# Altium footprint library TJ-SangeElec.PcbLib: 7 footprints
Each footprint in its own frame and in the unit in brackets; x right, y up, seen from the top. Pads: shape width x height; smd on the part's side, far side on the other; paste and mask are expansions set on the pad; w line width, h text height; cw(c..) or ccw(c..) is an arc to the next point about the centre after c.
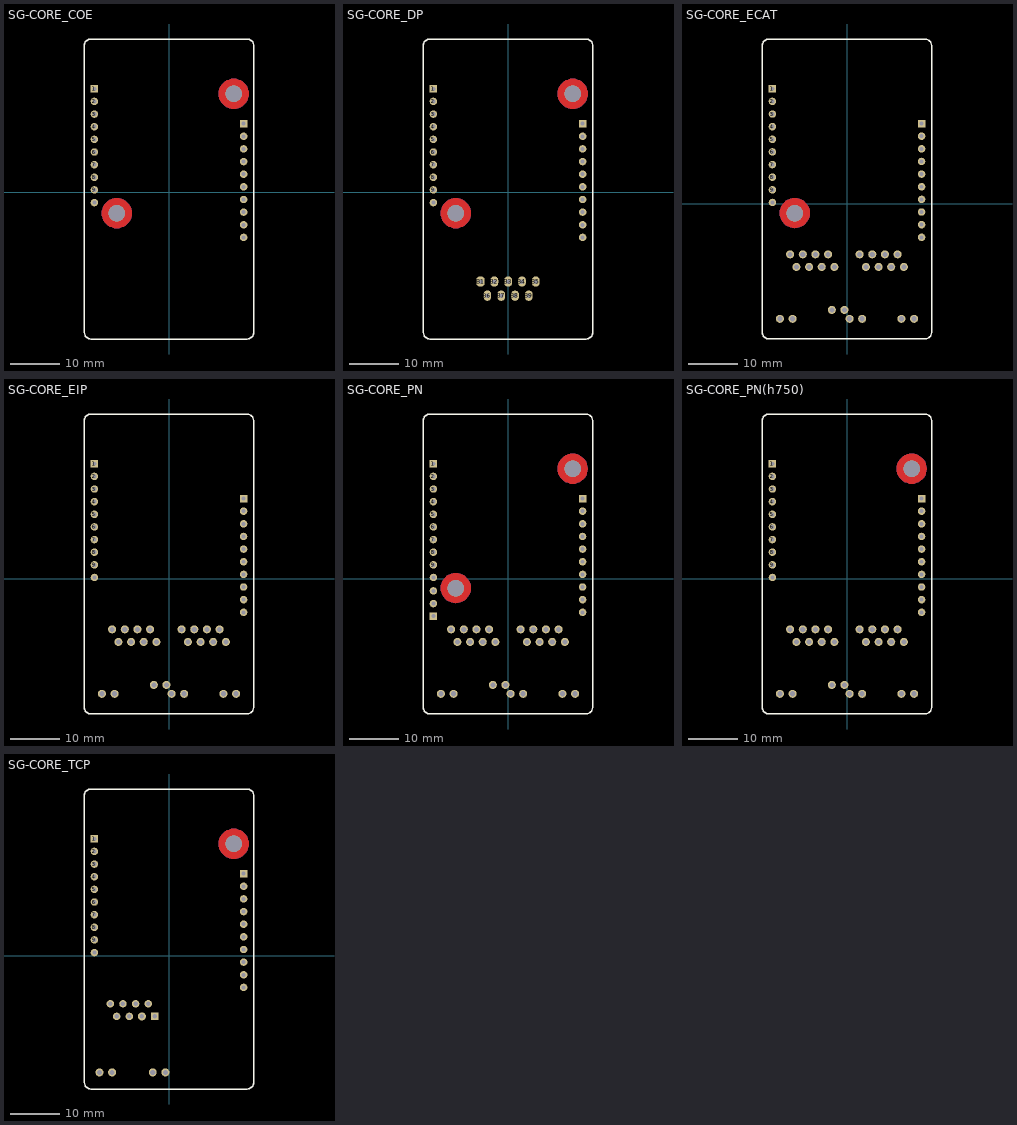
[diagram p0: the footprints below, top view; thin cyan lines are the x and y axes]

## SG-CORE_COE [mm] "CANOPEN核心板"
pads (20):
  rect 1.5x1.5 hole 0.8: 1(-15,20.783) 11(15,13.783)
  round 1.5 hole 0.8: 2(-15,18.243) 3(-15,15.703) 4(-15,13.163) 5(-15,10.623) 6(-15,8.083) 7(-15,5.543) 8(-15,3.003) 9(-15,0.463) 10(-15,-2.077) 12(15,11.243) 13(15,8.703) 14(15,6.163) 15(15,3.623) 16(15,1.083) 17(15,-1.457) 18(15,-3.997) 19(15,-6.537) 20(15,-9.077)
via -10.5,-4.217 diameter 3.3 hole 3.3
via 13,19.783 diameter 3.3 hole 3.3
Top Layer:
  pour cut-out: -13.509,-4.217 -13.472,-4.688 -13.362,-5.147 -13.181,-5.584 -12.935,-5.986 -12.628,-6.345 -12.269,-6.652 -11.866,-6.899 -11.43,-7.079 -10.971,-7.19 -10.5,-7.227 -10.029,-7.19 -9.57,-7.079 -9.134,-6.899 -8.731,-6.652 -8.372,-6.345 -8.065,-5.986 -7.819,-5.584 -7.638,-5.147 -7.528,-4.688 -7.491,-4.217 -7.528,-3.747 -7.638,-3.287 -7.819,-2.851 -8.065,-2.449 -8.372,-2.09 -8.731,-1.783 -9.134,-1.536 -9.57,-1.355 -10.029,-1.245 -10.5,-1.208 -10.971,-1.245 -11.43,-1.355 -11.866,-1.536 -12.269,-1.783 -12.628,-2.09 -12.935,-2.449 -13.181,-2.851 -13.362,-3.287 -13.472,-3.747
  pour cut-out: 9.991,19.783 10.028,19.312 10.138,18.853 10.319,18.416 10.565,18.014 10.872,17.655 11.231,17.348 11.634,17.101 12.07,16.921 12.529,16.81 13,16.773 13.471,16.81 13.93,16.921 14.366,17.101 14.769,17.348 15.128,17.655 15.435,18.014 15.681,18.416 15.862,18.853 15.972,19.312 16.009,19.783 15.972,20.253 15.862,20.713 15.681,21.149 15.435,21.551 15.128,21.91 14.769,22.217 14.366,22.464 13.93,22.645 13.471,22.755 13,22.792 12.529,22.755 12.07,22.645 11.634,22.464 11.231,22.217 10.872,21.91 10.565,21.551 10.319,21.149 10.138,20.713 10.028,20.253
Bottom Layer:
  pour cut-out: -13.509,-4.217 -13.472,-4.688 -13.362,-5.147 -13.181,-5.584 -12.935,-5.986 -12.628,-6.345 -12.269,-6.652 -11.866,-6.899 -11.43,-7.079 -10.971,-7.19 -10.5,-7.227 -10.029,-7.19 -9.57,-7.079 -9.134,-6.899 -8.731,-6.652 -8.372,-6.345 -8.065,-5.986 -7.819,-5.584 -7.638,-5.147 -7.528,-4.688 -7.491,-4.217 -7.528,-3.747 -7.638,-3.287 -7.819,-2.851 -8.065,-2.449 -8.372,-2.09 -8.731,-1.783 -9.134,-1.536 -9.57,-1.355 -10.029,-1.245 -10.5,-1.208 -10.971,-1.245 -11.43,-1.355 -11.866,-1.536 -12.269,-1.783 -12.628,-2.09 -12.935,-2.449 -13.181,-2.851 -13.362,-3.287 -13.472,-3.747
  pour cut-out: 9.991,19.783 10.028,19.312 10.138,18.853 10.319,18.416 10.565,18.014 10.872,17.655 11.231,17.348 11.634,17.101 12.07,16.921 12.529,16.81 13,16.773 13.471,16.81 13.93,16.921 14.366,17.101 14.769,17.348 15.128,17.655 15.435,18.014 15.681,18.416 15.862,18.853 15.972,19.312 16.009,19.783 15.972,20.253 15.862,20.713 15.681,21.149 15.435,21.551 15.128,21.91 14.769,22.217 14.366,22.464 13.93,22.645 13.471,22.755 13,22.792 12.529,22.755 12.07,22.645 11.634,22.464 11.231,22.217 10.872,21.91 10.565,21.551 10.319,21.149 10.138,20.713 10.028,20.253
Top Overlay:
  lines w0.254: -17.007,29.505 cw(c-15.737,29.505) -15.737,30.775 ; -17,-28.222 -17,29.512 ; -16.993,-28.222 ccw(c-15.723,-28.222) -15.723,-29.492 ; -15.73,30.79 15.723,30.79 ; -15.697,-29.492 0.025,-29.492 ; -0.152,-29.492 15.621,-29.492 ; 15.723,-29.492 ccw(c15.723,-28.222) 16.993,-28.222 ; 15.723,30.772 cw(c15.723,29.502) 16.993,29.502 ; 17,-28.222 17,29.509

## SG-CORE_DP [mm] "Profibus DP核心板"
pads (29):
  rect 1.5x1.5 hole 0.8: 1(-15,20.783) 11(15,13.783)
  round 1.5 hole 0.8: 2(-15,18.243) 3(-15,15.703) 4(-15,13.163) 5(-15,10.623) 6(-15,8.083) 7(-15,5.543) 8(-15,3.003) 9(-15,0.463) 10(-15,-2.077) 12(15,11.243) 13(15,8.703) 14(15,6.163) 15(15,3.623) 16(15,1.083) 17(15,-1.457) 18(15,-3.997) 19(15,-6.537) 20(15,-9.077)
  oct 1.575x2.083 hole 0.889: B1(-5.521,-17.946)
  oval 1.575x2.083 hole 0.889: B2(-2.748,-17.946) B3(0.025,-17.946) B4(2.797,-17.946) B5(5.57,-17.946) B7(-1.372,-20.783) B8(1.4,-20.783) B9(4.173,-20.783)
  oval 1.524x2.083 hole 0.889: B6(-4.145,-20.783)
via 13,19.783 diameter 3.3 hole 3.3
via -10.5,-4.217 diameter 3.3 hole 3.3
Top Layer:
  pour cut-out: 9.991,19.783 10.028,19.312 10.138,18.853 10.319,18.416 10.565,18.014 10.872,17.655 11.231,17.348 11.634,17.101 12.07,16.921 12.529,16.81 13,16.773 13.471,16.81 13.93,16.921 14.366,17.101 14.769,17.348 15.128,17.655 15.435,18.014 15.681,18.416 15.862,18.853 15.972,19.312 16.009,19.783 15.972,20.253 15.862,20.713 15.681,21.149 15.435,21.551 15.128,21.91 14.769,22.217 14.366,22.464 13.93,22.645 13.471,22.755 13,22.792 12.529,22.755 12.07,22.645 11.634,22.464 11.231,22.217 10.872,21.91 10.565,21.551 10.319,21.149 10.138,20.713 10.028,20.253
  pour cut-out: -13.509,-4.217 -13.472,-4.688 -13.362,-5.147 -13.181,-5.584 -12.935,-5.986 -12.628,-6.345 -12.269,-6.652 -11.866,-6.899 -11.43,-7.079 -10.971,-7.19 -10.5,-7.227 -10.029,-7.19 -9.57,-7.079 -9.134,-6.899 -8.731,-6.652 -8.372,-6.345 -8.065,-5.986 -7.819,-5.584 -7.638,-5.147 -7.528,-4.688 -7.491,-4.217 -7.528,-3.747 -7.638,-3.287 -7.819,-2.851 -8.065,-2.449 -8.372,-2.09 -8.731,-1.783 -9.134,-1.536 -9.57,-1.355 -10.029,-1.245 -10.5,-1.208 -10.971,-1.245 -11.43,-1.355 -11.866,-1.536 -12.269,-1.783 -12.628,-2.09 -12.935,-2.449 -13.181,-2.851 -13.362,-3.287 -13.472,-3.747
Bottom Layer:
  pour cut-out: 9.991,19.783 10.028,19.312 10.138,18.853 10.319,18.416 10.565,18.014 10.872,17.655 11.231,17.348 11.634,17.101 12.07,16.921 12.529,16.81 13,16.773 13.471,16.81 13.93,16.921 14.366,17.101 14.769,17.348 15.128,17.655 15.435,18.014 15.681,18.416 15.862,18.853 15.972,19.312 16.009,19.783 15.972,20.253 15.862,20.713 15.681,21.149 15.435,21.551 15.128,21.91 14.769,22.217 14.366,22.464 13.93,22.645 13.471,22.755 13,22.792 12.529,22.755 12.07,22.645 11.634,22.464 11.231,22.217 10.872,21.91 10.565,21.551 10.319,21.149 10.138,20.713 10.028,20.253
  pour cut-out: -13.509,-4.217 -13.472,-4.688 -13.362,-5.147 -13.181,-5.584 -12.935,-5.986 -12.628,-6.345 -12.269,-6.652 -11.866,-6.899 -11.43,-7.079 -10.971,-7.19 -10.5,-7.227 -10.029,-7.19 -9.57,-7.079 -9.134,-6.899 -8.731,-6.652 -8.372,-6.345 -8.065,-5.986 -7.819,-5.584 -7.638,-5.147 -7.528,-4.688 -7.491,-4.217 -7.528,-3.747 -7.638,-3.287 -7.819,-2.851 -8.065,-2.449 -8.372,-2.09 -8.731,-1.783 -9.134,-1.536 -9.57,-1.355 -10.029,-1.245 -10.5,-1.208 -10.971,-1.245 -11.43,-1.355 -11.866,-1.536 -12.269,-1.783 -12.628,-2.09 -12.935,-2.449 -13.181,-2.851 -13.362,-3.287 -13.472,-3.747
Top Overlay:
  lines w0.254: -17.007,29.505 cw(c-15.737,29.505) -15.737,30.775 ; -17,-28.222 -17,29.512 ; -16.993,-28.222 ccw(c-15.723,-28.222) -15.723,-29.492 ; -15.73,30.79 15.723,30.79 ; -15.697,-29.492 0.025,-29.492 ; -0.152,-29.492 15.621,-29.492 ; 15.723,-29.492 ccw(c15.723,-28.222) 16.993,-28.222 ; 15.723,30.772 cw(c15.723,29.502) 16.993,29.502 ; 17,-28.222 17,29.509

## SG-CORE_ECAT [mm] "EtherCAT核心板"
pads (44):
  rect 1.5x1.5 hole 0.8: 1(-15,23.122) 11(15,16.122)
  round 1.5 hole 0.8: 2(-15,20.582) 3(-15,18.042) 4(-15,15.502) 5(-15,12.962) 6(-15,10.422) 7(-15,7.882) 8(-15,5.342) 9(-15,2.802) 10(-15,0.262) 12(15,13.582) 13(15,11.042) 14(15,8.502) 15(15,5.962) 16(15,3.422) 17(15,0.882) 18(15,-1.658) 19(15,-4.198) 20(15,-6.738)
  round 1.62 hole 1.02: A1(11.43,-12.708) A2(10.16,-10.168) A3(8.89,-12.708) A4(7.62,-10.168) A5(6.35,-12.708) A6(5.08,-10.168) A7(3.81,-12.708) A8(2.54,-10.168) A9(13.487,-23.122) A10(10.947,-23.122) A11(3.048,-23.122) A12(0.508,-23.122) B1(-2.54,-12.708) B2(-3.81,-10.168) B3(-5.08,-12.708) B4(-6.35,-10.168) B5(-7.62,-12.708) B6(-8.89,-10.168) B7(-10.16,-12.708) B8(-11.43,-10.168) B9(-0.508,-21.344) B10(-3.048,-21.344) B11(-10.947,-23.122) B12(-13.487,-23.122)
via -10.5,-1.878 diameter 3.3 hole 3.3
Top Layer:
  pour cut-out: -13.509,-1.878 -13.472,-2.349 -13.362,-2.808 -13.181,-3.244 -12.935,-3.647 -12.628,-4.006 -12.269,-4.313 -11.866,-4.559 -11.43,-4.74 -10.971,-4.85 -10.5,-4.887 -10.029,-4.85 -9.57,-4.74 -9.134,-4.559 -8.731,-4.313 -8.372,-4.006 -8.065,-3.647 -7.819,-3.244 -7.638,-2.808 -7.528,-2.349 -7.491,-1.878 -7.528,-1.407 -7.638,-0.948 -7.819,-0.512 -8.065,-0.109 -8.372,0.25 -8.731,0.556 -9.134,0.803 -9.57,0.984 -10.029,1.094 -10.5,1.131 -10.971,1.094 -11.43,0.984 -11.866,0.803 -12.269,0.556 -12.628,0.25 -12.935,-0.109 -13.181,-0.512 -13.362,-0.948 -13.472,-1.407
Bottom Layer:
  pour cut-out: -13.509,-1.878 -13.472,-2.349 -13.362,-2.808 -13.181,-3.244 -12.935,-3.647 -12.628,-4.006 -12.269,-4.313 -11.866,-4.559 -11.43,-4.74 -10.971,-4.85 -10.5,-4.887 -10.029,-4.85 -9.57,-4.74 -9.134,-4.559 -8.731,-4.313 -8.372,-4.006 -8.065,-3.647 -7.819,-3.244 -7.638,-2.808 -7.528,-2.349 -7.491,-1.878 -7.528,-1.407 -7.638,-0.948 -7.819,-0.512 -8.065,-0.109 -8.372,0.25 -8.731,0.556 -9.134,0.803 -9.57,0.984 -10.029,1.094 -10.5,1.131 -10.971,1.094 -11.43,0.984 -11.866,0.803 -12.269,0.556 -12.628,0.25 -12.935,-0.109 -13.181,-0.512 -13.362,-0.948 -13.472,-1.407
Top Overlay:
  lines w0.254: -17,-25.908 ccw(c-15.73,-25.908) -15.73,-27.178 ; -17,-25.883 -17,31.844 ; -17,31.852 cw(c-15.73,31.852) -15.73,33.122 15.723,33.122 cw(c15.723,31.852) 16.993,31.852 ; -15.672,-27.186 15.781,-27.186 ; 15.723,-27.178 ccw(c15.723,-25.908) 16.993,-25.908 ; 17,-25.908 17,31.841

## SG-CORE_EIP [mm] "EtherNet核心板"
pads (44):
  rect 1.5x1.5 hole 0.8: 1(-15,23.122) 11(15,16.122)
  round 1.5 hole 0.8: 2(-15,20.582) 3(-15,18.042) 4(-15,15.502) 5(-15,12.962) 6(-15,10.422) 7(-15,7.882) 8(-15,5.342) 9(-15,2.802) 10(-15,0.262) 12(15,13.582) 13(15,11.042) 14(15,8.502) 15(15,5.962) 16(15,3.422) 17(15,0.882) 18(15,-1.658) 19(15,-4.198) 20(15,-6.738)
  round 1.62 hole 1.02: A1(11.43,-12.708) A2(10.16,-10.168) A3(8.89,-12.708) A4(7.62,-10.168) A5(6.35,-12.708) A6(5.08,-10.168) A7(3.81,-12.708) A8(2.54,-10.168) A9(13.487,-23.122) A10(10.947,-23.122) A11(3.048,-23.122) A12(0.508,-23.122) B1(-2.54,-12.708) B2(-3.81,-10.168) B3(-5.08,-12.708) B4(-6.35,-10.168) B5(-7.62,-12.708) B6(-8.89,-10.168) B7(-10.16,-12.708) B8(-11.43,-10.168) B9(-0.508,-21.344) B10(-3.048,-21.344) B11(-10.947,-23.122) B12(-13.487,-23.122)
Top Overlay:
  lines w0.254: -17,-25.908 ccw(c-15.73,-25.908) -15.73,-27.178 ; -17,-25.883 -17,31.844 ; -17,31.852 cw(c-15.73,31.852) -15.73,33.122 15.723,33.122 cw(c15.723,31.852) 16.993,31.852 ; -15.672,-27.186 15.781,-27.186 ; 15.723,-27.178 ccw(c15.723,-25.908) 16.993,-25.908 ; 17,-25.908 17,31.841

## SG-CORE_PN [mm] "Profinet核心板"
pads (47):
  rect 1.5x1.5 hole 0.8: 1(-15,23.122) 11(15,16.122) 23(-15,-7.526)
  round 1.5 hole 0.8: 2(-15,20.582) 3(-15,18.042) 4(-15,15.502) 5(-15,12.962) 6(-15,10.422) 7(-15,7.882) 8(-15,5.342) 9(-15,2.802) 10(-15,0.262) 12(15,13.582) 13(15,11.042) 14(15,8.502) 15(15,5.962) 16(15,3.422) 17(15,0.882) 18(15,-1.658) 19(15,-4.198) 20(15,-6.738) 21(-15,-2.446) 22(-15,-4.986)
  round 1.62 hole 1.02: A1(11.43,-12.708) A2(10.16,-10.168) A3(8.89,-12.708) A4(7.62,-10.168) A5(6.35,-12.708) A6(5.08,-10.168) A7(3.81,-12.708) A8(2.54,-10.168) A9(13.487,-23.122) A10(10.947,-23.122) A11(3.048,-23.122) A12(0.508,-23.122) B1(-2.54,-12.708) B2(-3.81,-10.168) B3(-5.08,-12.708) B4(-6.35,-10.168) B5(-7.62,-12.708) B6(-8.89,-10.168) B7(-10.16,-12.708) B8(-11.43,-10.168) B9(-0.508,-21.344) B10(-3.048,-21.344) B11(-10.947,-23.122) B12(-13.487,-23.122)
via 13,22.122 diameter 3.3 hole 3.3
via -10.5,-1.878 diameter 3.3 hole 3.3
Top Layer:
  pour cut-out: 9.991,22.122 10.028,21.651 10.138,21.192 10.319,20.756 10.565,20.353 10.872,19.994 11.231,19.687 11.634,19.441 12.07,19.26 12.529,19.15 13,19.113 13.471,19.15 13.93,19.26 14.366,19.441 14.769,19.687 15.128,19.994 15.435,20.353 15.681,20.756 15.862,21.192 15.972,21.651 16.009,22.122 15.972,22.593 15.862,23.052 15.681,23.488 15.435,23.891 15.128,24.25 14.769,24.556 14.366,24.803 13.93,24.984 13.471,25.094 13,25.131 12.529,25.094 12.07,24.984 11.634,24.803 11.231,24.556 10.872,24.25 10.565,23.891 10.319,23.488 10.138,23.052 10.028,22.593
  pour cut-out: -13.509,-1.878 -13.472,-2.349 -13.362,-2.808 -13.181,-3.244 -12.935,-3.647 -12.628,-4.006 -12.269,-4.313 -11.866,-4.559 -11.43,-4.74 -10.971,-4.85 -10.5,-4.887 -10.029,-4.85 -9.57,-4.74 -9.134,-4.559 -8.731,-4.313 -8.372,-4.006 -8.065,-3.647 -7.819,-3.244 -7.638,-2.808 -7.528,-2.349 -7.491,-1.878 -7.528,-1.407 -7.638,-0.948 -7.819,-0.512 -8.065,-0.109 -8.372,0.25 -8.731,0.556 -9.134,0.803 -9.57,0.984 -10.029,1.094 -10.5,1.131 -10.971,1.094 -11.43,0.984 -11.866,0.803 -12.269,0.556 -12.628,0.25 -12.935,-0.109 -13.181,-0.512 -13.362,-0.948 -13.472,-1.407
Bottom Layer:
  pour cut-out: 9.991,22.122 10.028,21.651 10.138,21.192 10.319,20.756 10.565,20.353 10.872,19.994 11.231,19.687 11.634,19.441 12.07,19.26 12.529,19.15 13,19.113 13.471,19.15 13.93,19.26 14.366,19.441 14.769,19.687 15.128,19.994 15.435,20.353 15.681,20.756 15.862,21.192 15.972,21.651 16.009,22.122 15.972,22.593 15.862,23.052 15.681,23.488 15.435,23.891 15.128,24.25 14.769,24.556 14.366,24.803 13.93,24.984 13.471,25.094 13,25.131 12.529,25.094 12.07,24.984 11.634,24.803 11.231,24.556 10.872,24.25 10.565,23.891 10.319,23.488 10.138,23.052 10.028,22.593
  pour cut-out: -13.509,-1.878 -13.472,-2.349 -13.362,-2.808 -13.181,-3.244 -12.935,-3.647 -12.628,-4.006 -12.269,-4.313 -11.866,-4.559 -11.43,-4.74 -10.971,-4.85 -10.5,-4.887 -10.029,-4.85 -9.57,-4.74 -9.134,-4.559 -8.731,-4.313 -8.372,-4.006 -8.065,-3.647 -7.819,-3.244 -7.638,-2.808 -7.528,-2.349 -7.491,-1.878 -7.528,-1.407 -7.638,-0.948 -7.819,-0.512 -8.065,-0.109 -8.372,0.25 -8.731,0.556 -9.134,0.803 -9.57,0.984 -10.029,1.094 -10.5,1.131 -10.971,1.094 -11.43,0.984 -11.866,0.803 -12.269,0.556 -12.628,0.25 -12.935,-0.109 -13.181,-0.512 -13.362,-0.948 -13.472,-1.407
Top Overlay:
  lines w0.254: -17,-25.908 ccw(c-15.73,-25.908) -15.73,-27.178 ; -17,-25.883 -17,31.844 ; -17,31.852 cw(c-15.73,31.852) -15.73,33.122 15.723,33.122 cw(c15.723,31.852) 16.993,31.852 ; -15.672,-27.186 15.781,-27.186 ; 15.723,-27.178 ccw(c15.723,-25.908) 16.993,-25.908 ; 17,-25.908 17,31.841

## SG-CORE_PN(h750) [mm] "Profinet(h750)核心板"
pads (44):
  rect 1.5x1.5 hole 0.8: 1(-15,23.122) 11(15,16.122)
  round 1.5 hole 0.8: 2(-15,20.582) 3(-15,18.042) 4(-15,15.502) 5(-15,12.962) 6(-15,10.422) 7(-15,7.882) 8(-15,5.342) 9(-15,2.802) 10(-15,0.262) 12(15,13.582) 13(15,11.042) 14(15,8.502) 15(15,5.962) 16(15,3.422) 17(15,0.882) 18(15,-1.658) 19(15,-4.198) 20(15,-6.738)
  round 1.62 hole 1.02: A1(11.43,-12.708) A2(10.16,-10.168) A3(8.89,-12.708) A4(7.62,-10.168) A5(6.35,-12.708) A6(5.08,-10.168) A7(3.81,-12.708) A8(2.54,-10.168) A9(13.487,-23.122) A10(10.947,-23.122) A11(3.048,-23.122) A12(0.508,-23.122) B1(-2.54,-12.708) B2(-3.81,-10.168) B3(-5.08,-12.708) B4(-6.35,-10.168) B5(-7.62,-12.708) B6(-8.89,-10.168) B7(-10.16,-12.708) B8(-11.43,-10.168) B9(-0.508,-21.344) B10(-3.048,-21.344) B11(-10.947,-23.122) B12(-13.487,-23.122)
via 13,22.122 diameter 3.3 hole 3.3
Top Layer:
  pour cut-out: 9.991,22.122 10.028,21.651 10.138,21.192 10.319,20.756 10.565,20.353 10.872,19.994 11.231,19.687 11.634,19.441 12.07,19.26 12.529,19.15 13,19.113 13.471,19.15 13.93,19.26 14.366,19.441 14.769,19.687 15.128,19.994 15.435,20.353 15.681,20.756 15.862,21.192 15.972,21.651 16.009,22.122 15.972,22.593 15.862,23.052 15.681,23.488 15.435,23.891 15.128,24.25 14.769,24.556 14.366,24.803 13.93,24.984 13.471,25.094 13,25.131 12.529,25.094 12.07,24.984 11.634,24.803 11.231,24.556 10.872,24.25 10.565,23.891 10.319,23.488 10.138,23.052 10.028,22.593
Bottom Layer:
  pour cut-out: 9.991,22.122 10.028,21.651 10.138,21.192 10.319,20.756 10.565,20.353 10.872,19.994 11.231,19.687 11.634,19.441 12.07,19.26 12.529,19.15 13,19.113 13.471,19.15 13.93,19.26 14.366,19.441 14.769,19.687 15.128,19.994 15.435,20.353 15.681,20.756 15.862,21.192 15.972,21.651 16.009,22.122 15.972,22.593 15.862,23.052 15.681,23.488 15.435,23.891 15.128,24.25 14.769,24.556 14.366,24.803 13.93,24.984 13.471,25.094 13,25.131 12.529,25.094 12.07,24.984 11.634,24.803 11.231,24.556 10.872,24.25 10.565,23.891 10.319,23.488 10.138,23.052 10.028,22.593
Top Overlay:
  lines w0.254: -17,-25.908 ccw(c-15.73,-25.908) -15.73,-27.178 ; -17,-25.883 -17,31.844 ; -17,31.852 cw(c-15.73,31.852) -15.73,33.122 15.723,33.122 cw(c15.723,31.852) 16.993,31.852 ; -15.672,-27.186 15.781,-27.186 ; 15.723,-27.178 ccw(c15.723,-25.908) 16.993,-25.908 ; 17,-25.908 17,31.841

## SG-CORE_TCP [mm] "TCP核心板"
pads (32):
  rect 1.5x1.5 hole 0.8: 1(-15,23.47) 11(15,16.47)
  round 1.5 hole 0.8: 2(-15,20.93) 3(-15,18.39) 4(-15,15.85) 5(-15,13.31) 6(-15,10.77) 7(-15,8.23) 8(-15,5.69) 9(-15,3.15) 10(-15,0.61) 12(15,13.93) 13(15,11.39) 14(15,8.85) 15(15,6.31) 16(15,3.77) 17(15,1.23) 18(15,-1.31) 19(15,-3.85) 20(15,-6.39)
  rect 1.5x1.5 hole 0.9: B1(-2.902,-12.22)
  round 1.5 hole 0.9: B2(-4.172,-9.68) B4(-6.712,-9.68) B5(-7.982,-12.22) B6(-9.252,-9.68) B7(-10.522,-12.22) B8(-11.792,-9.68)
  round 1.6 hole 0.9: B3(-5.442,-12.22)
  round 1.6 hole 1.02: B9(-0.727,-23.47) B10(-3.267,-23.47) B11(-11.437,-23.47) B12(-13.977,-23.47)
via 13,22.47 diameter 3.3 hole 3.3
Top Layer:
  pour cut-out: 9.991,22.47 10.028,21.999 10.138,21.54 10.319,21.104 10.565,20.701 10.872,20.342 11.231,20.036 11.634,19.789 12.07,19.608 12.529,19.498 13,19.461 13.471,19.498 13.93,19.608 14.366,19.789 14.769,20.036 15.128,20.342 15.435,20.701 15.681,21.104 15.862,21.54 15.972,21.999 16.009,22.47 15.972,22.941 15.862,23.4 15.681,23.836 15.435,24.239 15.128,24.598 14.769,24.905 14.366,25.151 13.93,25.332 13.471,25.442 13,25.479 12.529,25.442 12.07,25.332 11.634,25.151 11.231,24.905 10.872,24.598 10.565,24.239 10.319,23.836 10.138,23.4 10.028,22.941
Bottom Layer:
  pour cut-out: 9.991,22.47 10.028,21.999 10.138,21.54 10.319,21.104 10.565,20.701 10.872,20.342 11.231,20.036 11.634,19.789 12.07,19.608 12.529,19.498 13,19.461 13.471,19.498 13.93,19.608 14.366,19.789 14.769,20.036 15.128,20.342 15.435,20.701 15.681,21.104 15.862,21.54 15.972,21.999 16.009,22.47 15.972,22.941 15.862,23.4 15.681,23.836 15.435,24.239 15.128,24.598 14.769,24.905 14.366,25.151 13.93,25.332 13.471,25.442 13,25.479 12.529,25.442 12.07,25.332 11.634,25.151 11.231,24.905 10.872,24.598 10.565,24.239 10.319,23.836 10.138,23.4 10.028,22.941
Top Overlay:
  lines w0.254: -17.007,32.192 cw(c-15.737,32.192) -15.737,33.462 ; -17,-25.534 -17,32.2 ; -16.993,-25.534 ccw(c-15.723,-25.534) -15.723,-26.804 ; -15.73,33.478 15.723,33.478 ; -15.697,-26.804 0.025,-26.804 ; -0.152,-26.804 15.621,-26.804 ; 15.723,-26.804 ccw(c15.723,-25.534) 16.993,-25.534 ; 15.723,33.459 cw(c15.723,32.189) 16.993,32.189 ; 17,-25.534 17,32.197
Bottom Overlay:
  text "Y" at -10.654,-24.793 h0.8
  text "G" at -4.939,-24.793 h0.8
